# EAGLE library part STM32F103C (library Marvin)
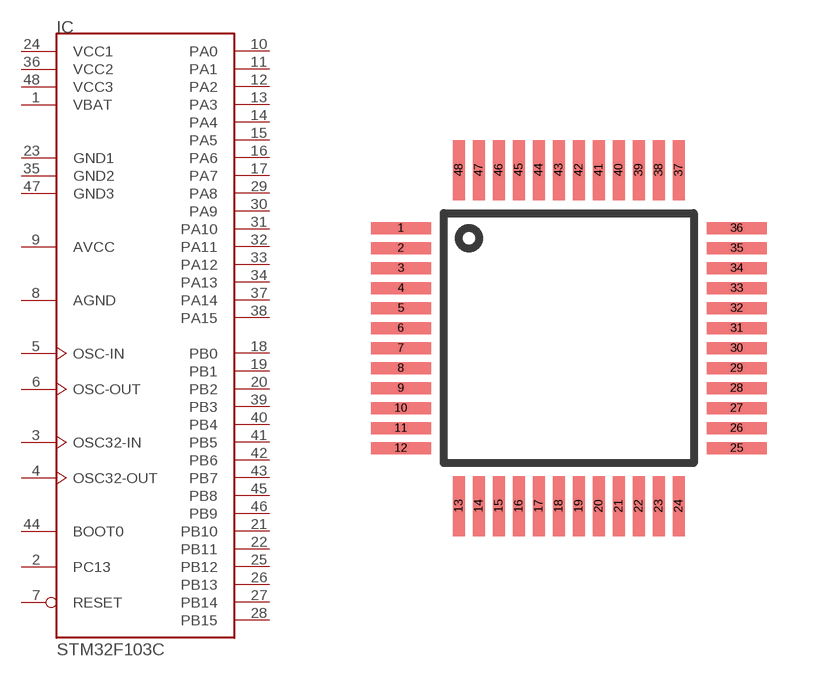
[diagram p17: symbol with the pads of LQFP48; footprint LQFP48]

Designator prefix IC

## STM32F103C  [LQFP48]
1  VBAT  pwr
2  PC13
3  OSC32-IN  in
4  OSC32-OUT  out
5  OSC-IN  in
6  OSC-OUT  out
7  RESET
8  AGND  pwr
9  AVCC  pwr
10  PA0
11  PA1
12  PA2
13  PA3
14  PA4
15  PA5
16  PA6
17  PA7
18  PB0
19  PB1
20  PB2
21  PB10
22  PB11
23  GND1  pwr
24  VCC1  pwr
25  PB12
26  PB13
27  PB14
28  PB15
29  PA8
30  PA9
31  PA10
32  PA11
33  PA12
34  PA13
35  GND2  pwr
36  VCC2  pwr
37  PA14
38  PA15
39  PB3
40  PB4
41  PB5
42  PB6
43  PB7
44  BOOT0
45  PB8
46  PB9
47  GND3  pwr
48  VCC3  pwr

## Footprint LQFP48 (pad centres in mm)
smd 1.5 x 0.3: 1 -4.2,2.75; 2 -4.2,2.25; 3 -4.2,1.75; 4 -4.2,1.25; 5 -4.2,0.75; 6 -4.2,0.25; 7 -4.2,-0.25; 8 -4.2,-0.75; 9 -4.2,-1.25; 10 -4.2,-1.75; 11 -4.2,-2.25; 12 -4.2,-2.75; 25 4.2,-2.75; 26 4.2,-2.25; 27 4.2,-1.75; 28 4.2,-1.25; 29 4.2,-0.75; 30 4.2,-0.25; 31 4.2,0.25; 32 4.2,0.75; 33 4.2,1.25; 34 4.2,1.75; 35 4.2,2.25; 36 4.2,2.75
smd 0.3 x 1.5: 13 -2.75,-4.2; 14 -2.25,-4.2; 15 -1.75,-4.2; 16 -1.25,-4.2; 17 -0.75,-4.2; 18 -0.25,-4.2; 19 0.25,-4.2; 20 0.75,-4.2; 21 1.25,-4.2; 22 1.75,-4.2; 23 2.25,-4.2; 24 2.75,-4.2; 37 2.75,4.2; 38 2.25,4.2; 39 1.75,4.2; 40 1.25,4.2; 41 0.75,4.2; 42 0.25,4.2; 43 -0.25,4.2; 44 -0.75,4.2; 45 -1.25,4.2; 46 -1.75,4.2; 47 -2.25,4.2; 48 -2.75,4.2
